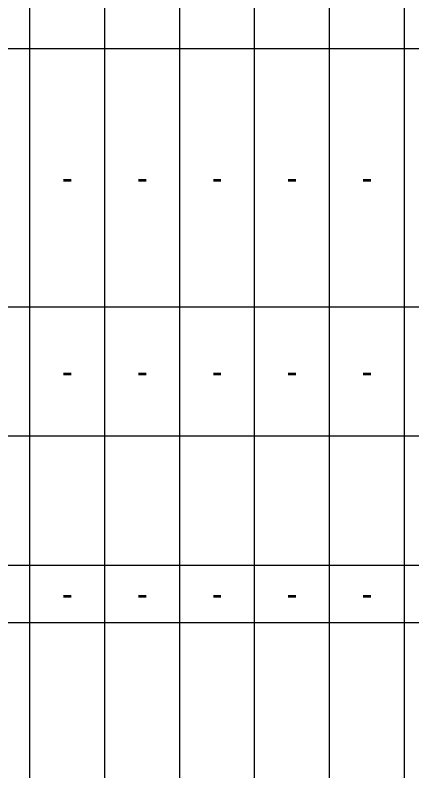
# Model space of a CAD drawing. Extents: x 0 to 0.83, y -0.65 to 1.27.
# Drawn here: x 0.6168 to 0.7272, y 0.4451 to 0.655 of the extents above; entities that cross this region are included whole.
import ezdxf

# ---------------------------------------------------------------- set-up
doc = ezdxf.new("R2010")
doc.units = 0

msp = doc.modelspace()

# ---------------------------------------------------------------- linework, layer by layer
for points in [[(0.6625, 1.22083), (0.6625, -0.64575)], [(0.725, 1.22083), (0.725, -0.64575)], [(0.62083, 1.20833), (0.62083, -0.64575)], [(0.64167, 1.20833), (0.64167, -0.64575)], [(0.68333, 1.20833), (0.68333, -0.64575)], [(0.70417, 1.20833), (0.70417, -0.64575)], [(0.725, 1.20833), (0.725, -0.64575)], [(0.6, 0.64575), (0.62083, 0.64575)], [(0.62083, 0.64575), (0.64167, 0.64575)], [(0.64167, 0.64575), (0.6625, 0.64575)], [(0.6625, 0.64575), (0.68333, 0.64575)], [(0.68333, 0.64575), (0.70417, 0.64575)], [(0.70417, 0.64575), (0.725, 0.64575)], [(0.725, 0.64575), (0.75, 0.64575)], [(0.6, 0.574), (0.62083, 0.574)], [(0.62083, 0.574), (0.64167, 0.574)], [(0.64167, 0.574), (0.6625, 0.574)], [(0.6625, 0.574), (0.68333, 0.574)], [(0.68333, 0.574), (0.70417, 0.574)], [(0.70417, 0.574), (0.725, 0.574)], [(0.725, 0.574), (0.75, 0.574)], [(0.6, 0.53812), (0.62083, 0.53812)], [(0.62083, 0.53812), (0.64167, 0.53812)], [(0.64167, 0.53812), (0.6625, 0.53812)], [(0.6625, 0.53812), (0.68333, 0.53812)], [(0.68333, 0.53812), (0.70417, 0.53812)], [(0.70417, 0.53812), (0.725, 0.53812)], [(0.725, 0.53812), (0.75, 0.53812)], [(0.6, 0.50225), (0.62083, 0.50225)], [(0.62083, 0.50225), (0.64167, 0.50225)], [(0.64167, 0.50225), (0.6625, 0.50225)], [(0.6625, 0.50225), (0.68333, 0.50225)], [(0.68333, 0.50225), (0.70417, 0.50225)], [(0.70417, 0.50225), (0.725, 0.50225)], [(0.725, 0.50225), (0.75, 0.50225)], [(0.6, 0.4863), (0.62083, 0.4863)], [(0.62083, 0.4863), (0.64167, 0.4863)], [(0.64167, 0.4863), (0.6625, 0.4863)], [(0.6625, 0.4863), (0.68333, 0.4863)], [(0.68333, 0.4863), (0.70417, 0.4863)], [(0.70417, 0.4863), (0.725, 0.4863)], [(0.725, 0.4863), (0.75, 0.4863)]]:
    msp.add_lwpolyline(points)

# ---------------------------------------------------------------- texts
for p in [(0.62984, 0.60654), (0.65068, 0.60654), (0.67151, 0.60654), (0.69234, 0.60654), (0.71318, 0.60654), (0.62984, 0.55273), (0.65068, 0.55273), (0.67151, 0.55273), (0.69234, 0.55273), (0.71318, 0.55273), (0.62984, 0.49094), (0.65068, 0.49094), (0.67151, 0.49094), (0.69234, 0.49094), (0.71318, 0.49094)]:
    msp.add_text('-', height=0.00667).set_placement(p)

doc.saveas('drawing.dxf')
